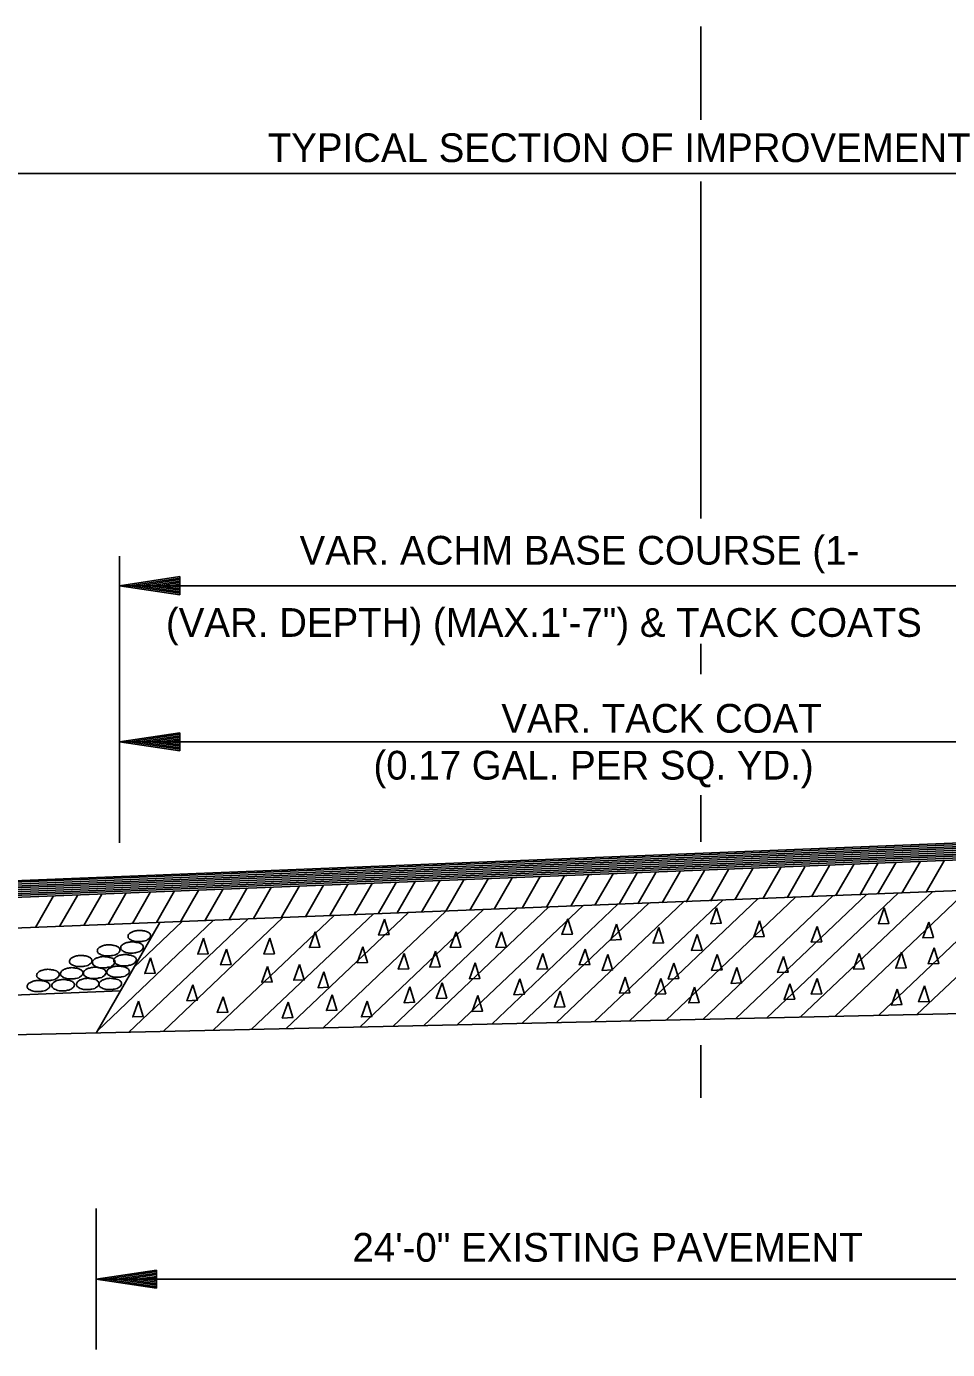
# Model space of a CAD drawing. Extents: x 714919 to 718439, y 1619644 to 1621844.
# Drawn here: x 716443 to 716828, y 1620734 to 1621286 of the extents above; entities that cross this region are included whole.
import ezdxf

# ---------------------------------------------------------------- set-up
doc = ezdxf.new("R2010")
doc.units = 0
doc.layers.add('R_Dimension', color=7, linetype='Continuous')
doc.layers.add('R_Draft', color=7, linetype='Continuous')

msp = doc.modelspace()

# ---------------------------------------------------------------- linework, layer by layer
at = {"layer": 'R_Dimension'}
for p, q in [((716083.88, 1621224.65), (717366.01, 1621224.65)), ((716482.09, 1620945.31), (716482.09, 1621064.99)), ((716507.22, 1621056.42), (716482.09, 1621052.6)), ((716482.09, 1621052.6), (716965.77, 1621052.6)), ((716507.22, 1621048.83), (716482.09, 1621052.6)), ((716507.22, 1621055.74), (716486.27, 1621052.6)), ((716507.22, 1621049.45), (716486.27, 1621052.6)), ((716507.22, 1621055.19), (716490.59, 1621052.6)), ((716507.22, 1621050.06), (716490.59, 1621052.6)), ((716507.22, 1621054.48), (716494.79, 1621052.6)), ((716507.22, 1621050.73), (716494.79, 1621052.6)), ((716507.22, 1621053.88), (716499.05, 1621052.6)), ((716507.22, 1621051.34), (716499.05, 1621052.6)), ((716507.22, 1621053.2), (716503.27, 1621052.6)), ((716507.22, 1621052.04), (716503.27, 1621052.6)), ((716507.22, 1621048.83), (716507.22, 1621056.42)), ((716507.22, 1620991.18), (716482.09, 1620987.43)), ((716482.09, 1620987.43), (716965.77, 1620987.43)), ((716507.22, 1620983.64), (716482.09, 1620987.43)), ((716507.22, 1620990.6), (716486.27, 1620987.43)), ((716507.22, 1620984.32), (716486.27, 1620987.43)), ((716507.22, 1620989.93), (716490.59, 1620987.43)), ((716507.22, 1620984.92), (716490.59, 1620987.43)), ((716507.22, 1620989.35), (716494.79, 1620987.43)), ((716507.22, 1620985.56), (716494.79, 1620987.43)), ((716507.22, 1620988.62), (716499.05, 1620987.43)), ((716507.22, 1620986.2), (716499.05, 1620987.43)), ((716507.22, 1620988.06), (716503.27, 1620987.43)), ((716507.22, 1620986.86), (716503.27, 1620987.43)), ((716507.22, 1620983.64), (716507.22, 1620991.18)), ((716472.35, 1620733.75), (716472.35, 1620792.61)), ((716497.51, 1620766.86), (716472.35, 1620763.08)), ((716497.51, 1620766.26), (716476.54, 1620763.08)), ((716497.51, 1620765.57), (716480.91, 1620763.08)), ((716497.51, 1620765.02), (716485.05, 1620763.08)), ((716497.51, 1620759.32), (716497.51, 1620766.86)), ((716472.35, 1620763.08), (716975.67, 1620763.08)), ((716497.51, 1620759.32), (716472.35, 1620763.08)), ((716497.51, 1620759.97), (716476.54, 1620763.08)), ((716497.51, 1620760.58), (716480.91, 1620763.08)), ((716497.51, 1620761.21), (716485.05, 1620763.08)), ((716497.51, 1620764.29), (716489.36, 1620763.08)), ((716497.51, 1620761.85), (716489.36, 1620763.08)), ((716497.51, 1620763.74), (716493.55, 1620763.08)), ((716497.51, 1620762.51), (716493.55, 1620763.08))]:
    msp.add_line(p, q, dxfattribs=at)
at = {"layer": 'R_Draft'}
for p, q in [((716724.7, 1621247.08), (716724.7, 1621286.06)), ((716724.7, 1621095.46), (716724.7, 1621221.36)), ((716724.7, 1621080.6), (716724.7, 1621095.46)), ((716724.7, 1621015.65), (716724.7, 1621028.27)), ((716077.33, 1620912.05), (717371.84, 1620963.68)), ((716079.01, 1620912.92), (717370.38, 1620964.41)), ((716080.68, 1620913.71), (717368.96, 1620965.14)), ((716082.38, 1620914.6), (717367.45, 1620965.87)), ((716083.88, 1620915.32), (717366.08, 1620966.55)), ((716724.7, 1620945.67), (716724.7, 1620965.11)), ((716273.48, 1620916.69), (717175.48, 1620952.65)), ((716273.96, 1620917.52), (717174.96, 1620953.41)), ((716274.45, 1620918.29), (717173.88, 1620954.11)), ((716274.98, 1620919.1), (717173.88, 1620954.98)), ((716272.93, 1620915.95), (717176, 1620951.88)), ((716264.68, 1620902.75), (717184.57, 1620939.35)), ((716788.45, 1620936.18), (716780.88, 1620923.13)), ((716798.54, 1620936.59), (716790.99, 1620923.47)), ((716805.99, 1620936.98), (716798.4, 1620923.79)), ((716816.15, 1620937.4), (716808.53, 1620924.2)), ((716826.18, 1620937.72), (716818.67, 1620924.68)), ((716645.95, 1620930.68), (716638.41, 1620917.55)), ((716657.63, 1620931.15), (716650.06, 1620917.97)), ((716667.67, 1620931.36), (716660.23, 1620918.44)), ((716677.95, 1620931.95), (716670.34, 1620918.87)), ((716688.02, 1620932.38), (716680.47, 1620919.2)), ((716698.14, 1620932.77), (716690.56, 1620919.62)), ((716705.93, 1620932.93), (716698.39, 1620919.8)), ((716716.08, 1620933.29), (716708.5, 1620920.22)), ((716726.15, 1620933.71), (716718.6, 1620920.56)), ((716736.25, 1620934.18), (716728.73, 1620920.98)), ((716746.37, 1620934.55), (716738.85, 1620921.43)), ((716758.09, 1620934.97), (716750.48, 1620921.83)), ((716768.13, 1620935.2), (716760.71, 1620922.26)), ((716778.31, 1620935.83), (716770.8, 1620922.66)), ((716505.06, 1620925.22), (716497.48, 1620912.08)), ((716515.21, 1620925.62), (716507.67, 1620912.5)), ((716525.27, 1620926.11), (716517.75, 1620912.94)), ((716535.4, 1620926.46), (716527.87, 1620913.31)), ((716545.46, 1620926.85), (716537.94, 1620913.7)), ((716557.19, 1620927.35), (716549.65, 1620914.18)), ((716567.26, 1620927.56), (716559.81, 1620914.6)), ((716577.42, 1620928.11), (716569.9, 1620914.98)), ((716587.57, 1620928.53), (716580.03, 1620915.4)), ((716597.63, 1620928.97), (716590.09, 1620915.85)), ((716605.51, 1620929.07), (716597.95, 1620915.98)), ((716615.71, 1620929.47), (716608.11, 1620916.3)), ((716625.74, 1620929.86), (716618.19, 1620916.74)), ((716635.87, 1620930.3), (716628.32, 1620917.16)), ((716780.54, 1620872.8), (716835.95, 1620925.47)), ((716798.88, 1620873.26), (716854.69, 1620926.28)), ((716814.85, 1620873.6), (716871.1, 1620926.87)), ((716454.51, 1620923.16), (716446.94, 1620909.98)), ((716464.53, 1620923.34), (716457.08, 1620910.4)), ((716474.72, 1620923.89), (716467.18, 1620910.79)), ((716484.88, 1620924.34), (716477.3, 1620911.22)), ((716494.97, 1620924.75), (716487.42, 1620911.64)), ((716637.39, 1620869.6), (716690.01, 1620919.68)), ((716650.01, 1620869.87), (716703.15, 1620920.23)), ((716664.24, 1620870.18), (716717.58, 1620920.72)), ((716680.18, 1620870.54), (716733.98, 1620921.45)), ((716694.69, 1620870.85), (716748.61, 1620922.03)), ((716710.25, 1620871.23), (716764.14, 1620922.61)), ((716725.54, 1620871.56), (716779.84, 1620923.29)), ((716739.32, 1620871.9), (716793.92, 1620923.79)), ((716752.04, 1620872.14), (716807.09, 1620924.34)), ((716766.16, 1620872.46), (716821.42, 1620924.91)), ((716500.28, 1620866.48), (716550.28, 1620914.1)), ((716521.08, 1620867), (716571.65, 1620914.93)), ((716537.05, 1620867.3), (716588.07, 1620915.62)), ((716551.48, 1620867.63), (716602.68, 1620916.16)), ((716567.05, 1620867.98), (716618.27, 1620916.8)), ((716582.33, 1620868.37), (716633.9, 1620917.5)), ((716596.11, 1620868.65), (716648.02, 1620917.97)), ((716608.89, 1620868.92), (716661.19, 1620918.55)), ((716622.99, 1620869.24), (716675.5, 1620919.08)), ((716472.35, 1620865.88), (716498.95, 1620912.07)), ((716472.89, 1620866.82), (716521.35, 1620913)), ((716485.81, 1620866.12), (716535.75, 1620913.49)), ((716488.15, 1620893.32), (716508.22, 1620912.42)), ((715980.19, 1620863.5), (716482.51, 1620883.51)), ((716371.46, 1620863.61), (717076.27, 1620879.47)), ((716724.7, 1620838.78), (716724.7, 1620860.75))]:
    msp.add_line(p, q, dxfattribs=at)
for points in [[(716731.19, 1620918.12), (716728.78, 1620911.49), (716733.17, 1620911.67), (716731.19, 1620918.12)], [(716801.2, 1620918.1), (716798.79, 1620911.47), (716803.18, 1620911.65), (716801.2, 1620918.1)], [(716592.6, 1620913.41), (716590.19, 1620906.78), (716594.58, 1620906.96), (716592.6, 1620913.41)], [(716669.13, 1620913.58), (716666.71, 1620906.95), (716671.1, 1620907.13), (716669.13, 1620913.58)], [(716689.48, 1620911.32), (716687.06, 1620904.69), (716691.46, 1620904.87), (716689.48, 1620911.32)], [(716707.12, 1620909.96), (716704.7, 1620903.33), (716709.1, 1620903.51), (716707.12, 1620909.96)], [(716749.19, 1620912.68), (716746.77, 1620906.05), (716751.16, 1620906.23), (716749.19, 1620912.68)], [(716773.16, 1620910.41), (716770.74, 1620903.78), (716775.14, 1620903.96), (716773.16, 1620910.41)], [(716819.75, 1620912.22), (716817.33, 1620905.59), (716821.72, 1620905.77), (716819.75, 1620912.22)], [(716517.15, 1620905.44), (716514.73, 1620898.81), (716519.12, 1620898.99), (716517.15, 1620905.44)], [(716544.74, 1620905.44), (716542.32, 1620898.81), (716546.72, 1620898.99), (716544.74, 1620905.44)], [(716563.74, 1620908.15), (716561.32, 1620901.52), (716565.71, 1620901.7), (716563.74, 1620908.15)], [(716622.54, 1620908.15), (716620.12, 1620901.52), (716624.51, 1620901.7), (716622.54, 1620908.15)], [(716641.53, 1620908.15), (716639.12, 1620901.52), (716643.51, 1620901.7), (716641.53, 1620908.15)], [(716723.17, 1620906.97), (716720.76, 1620900.34), (716725.15, 1620900.52), (716723.17, 1620906.97)], [(716526.65, 1620900.92), (716524.23, 1620894.29), (716528.62, 1620894.47), (716526.65, 1620900.92)], [(716583.64, 1620901.82), (716581.22, 1620895.19), (716585.61, 1620895.37), (716583.64, 1620901.82)], [(716600.83, 1620899.11), (716598.41, 1620892.48), (716602.8, 1620892.66), (716600.83, 1620899.11)], [(716613.94, 1620900.01), (716611.53, 1620893.38), (716615.92, 1620893.56), (716613.94, 1620900.01)], [(716658.72, 1620899.11), (716656.31, 1620892.48), (716660.7, 1620892.66), (716658.72, 1620899.11)], [(716676.36, 1620900.92), (716673.95, 1620894.29), (716678.34, 1620894.47), (716676.36, 1620900.92)], [(716685.86, 1620898.65), (716683.44, 1620892.02), (716687.84, 1620892.2), (716685.86, 1620898.65)], [(716731.54, 1620898.65), (716729.13, 1620892.02), (716733.52, 1620892.2), (716731.54, 1620898.65)], [(716759.14, 1620897.75), (716756.72, 1620891.12), (716761.11, 1620891.3), (716759.14, 1620897.75)], [(716790.8, 1620899.11), (716788.38, 1620892.48), (716792.78, 1620892.66), (716790.8, 1620899.11)], [(716808.44, 1620899.56), (716806.02, 1620892.93), (716810.42, 1620893.11), (716808.44, 1620899.56)], [(716822.01, 1620901.37), (716819.59, 1620894.74), (716823.99, 1620894.92), (716822.01, 1620901.37)], [(716494.98, 1620897.3), (716492.57, 1620890.67), (716496.96, 1620890.85), (716494.98, 1620897.3)], [(716543.83, 1620893.68), (716541.42, 1620887.05), (716545.81, 1620887.23), (716543.83, 1620893.68)], [(716557.2, 1620894.5), (716554.78, 1620887.87), (716559.17, 1620888.05), (716557.2, 1620894.5)], [(716630.51, 1620895.15), (716628.09, 1620888.52), (716632.49, 1620888.7), (716630.51, 1620895.15)], [(716713.45, 1620895.04), (716711.04, 1620888.41), (716715.43, 1620888.58), (716713.45, 1620895.04)], [(716739.69, 1620893.23), (716737.27, 1620886.6), (716741.66, 1620886.78), (716739.69, 1620893.23)], [(716567.35, 1620891.42), (716564.94, 1620884.79), (716569.33, 1620884.97), (716567.35, 1620891.42)], [(716616.66, 1620886.89), (716614.24, 1620880.26), (716618.63, 1620880.44), (716616.66, 1620886.89)], [(716649.07, 1620888.49), (716646.65, 1620881.86), (716651.05, 1620882.03), (716649.07, 1620888.49)], [(716693.1, 1620889.16), (716690.68, 1620882.53), (716695.08, 1620882.7), (716693.1, 1620889.16)], [(716708.02, 1620888.7), (716705.61, 1620882.07), (716710, 1620882.25), (716708.02, 1620888.7)], [(716761.85, 1620886.44), (716759.43, 1620879.81), (716763.83, 1620879.99), (716761.85, 1620886.44)], [(716773.16, 1620888.7), (716770.74, 1620882.07), (716775.14, 1620882.25), (716773.16, 1620888.7)], [(716512.62, 1620885.99), (716510.21, 1620879.36), (716514.6, 1620879.54), (716512.62, 1620885.99)], [(716525.29, 1620881.01), (716522.87, 1620874.38), (716527.27, 1620874.56), (716525.29, 1620881.01)], [(716570.8, 1620881.87), (716568.38, 1620875.23), (716572.77, 1620875.41), (716570.8, 1620881.87)], [(716603.23, 1620885.16), (716600.81, 1620878.53), (716605.21, 1620878.71), (716603.23, 1620885.16)], [(716631.58, 1620881.47), (716629.17, 1620874.84), (716633.56, 1620875.02), (716631.58, 1620881.47)], [(716665.96, 1620883.28), (716663.54, 1620876.64), (716667.94, 1620876.82), (716665.96, 1620883.28)], [(716722.05, 1620885.08), (716719.63, 1620878.45), (716724.02, 1620878.63), (716722.05, 1620885.08)], [(716806.63, 1620884.18), (716804.21, 1620877.55), (716808.61, 1620877.73), (716806.63, 1620884.18)], [(716817.94, 1620885.54), (716815.52, 1620878.91), (716819.91, 1620879.09), (716817.94, 1620885.54)], [(716490.01, 1620879.2), (716487.59, 1620872.57), (716491.98, 1620872.75), (716490.01, 1620879.2)], [(716552.43, 1620878.75), (716550.01, 1620872.12), (716554.4, 1620872.3), (716552.43, 1620878.75)], [(716585.45, 1620879.2), (716583.03, 1620872.57), (716587.42, 1620872.75), (716585.45, 1620879.2)]]:
    msp.add_lwpolyline(points, dxfattribs=at)
for points in [[(716490.32, 1620904.05), (716488.64, 1620904.08), (716486.81, 1620904.73), (716485.74, 1620905.63), (716485.63, 1620906.15), (716486.06, 1620907.27), (716486.69, 1620907.74), (716487.76, 1620908.27), (716489.4, 1620908.64), (716490.17, 1620908.72), (716491.45, 1620908.61), (716492.83, 1620908.4), (716493.89, 1620908.03), (716494.9, 1620907.17), (716495.07, 1620906.6), (716494.78, 1620905.67), (716494.02, 1620904.99), (716493.26, 1620904.52), (716492.11, 1620904.24), (716491.39, 1620904.08), (716490.32, 1620904.05)], [(716487.24, 1620899.26), (716485.56, 1620899.29), (716483.73, 1620899.94), (716482.66, 1620900.84), (716482.55, 1620901.36), (716482.98, 1620902.48), (716483.62, 1620902.95), (716484.68, 1620903.48), (716486.32, 1620903.85), (716487.09, 1620903.93), (716488.37, 1620903.82), (716489.75, 1620903.61), (716490.81, 1620903.24), (716491.82, 1620902.38), (716491.99, 1620901.82), (716491.7, 1620900.88), (716490.94, 1620900.2), (716490.18, 1620899.73), (716489.03, 1620899.45), (716488.31, 1620899.29), (716487.24, 1620899.26)], [(716465.86, 1620893.61), (716464.17, 1620893.65), (716462.35, 1620894.29), (716461.28, 1620895.2), (716461.17, 1620895.72), (716461.6, 1620896.83), (716462.23, 1620897.3), (716463.3, 1620897.84), (716464.93, 1620898.21), (716465.71, 1620898.29), (716466.99, 1620898.18), (716468.36, 1620897.97), (716469.43, 1620897.59), (716470.43, 1620896.74), (716470.61, 1620896.17), (716470.32, 1620895.23), (716469.56, 1620894.55), (716468.8, 1620894.08), (716467.65, 1620893.81), (716466.92, 1620893.65), (716465.86, 1620893.61)], [(716475.44, 1620893.1), (716473.75, 1620893.13), (716471.93, 1620893.78), (716470.86, 1620894.69), (716470.74, 1620895.2), (716471.18, 1620896.32), (716471.81, 1620896.79), (716472.88, 1620897.32), (716474.51, 1620897.7), (716475.29, 1620897.78), (716476.57, 1620897.66), (716477.94, 1620897.45), (716479.01, 1620897.08), (716480.01, 1620896.22), (716480.19, 1620895.66), (716479.9, 1620894.72), (716479.14, 1620894.04), (716478.38, 1620893.57), (716477.23, 1620893.3), (716476.5, 1620893.13), (716475.44, 1620893.1)], [(716477.49, 1620898.06), (716475.81, 1620898.09), (716473.98, 1620898.74), (716472.91, 1620899.65), (716472.8, 1620900.16), (716473.23, 1620901.28), (716473.87, 1620901.75), (716474.93, 1620902.28), (716476.57, 1620902.66), (716477.34, 1620902.74), (716478.62, 1620902.62), (716480, 1620902.41), (716481.06, 1620902.04), (716482.07, 1620901.18), (716482.24, 1620900.62), (716481.95, 1620899.68), (716481.19, 1620899), (716480.43, 1620898.53), (716479.28, 1620898.26), (716478.56, 1620898.09), (716477.49, 1620898.06)], [(716484.33, 1620893.96), (716482.65, 1620893.99), (716480.82, 1620894.64), (716479.75, 1620895.54), (716479.64, 1620896.06), (716480.08, 1620897.18), (716480.71, 1620897.64), (716481.77, 1620898.18), (716483.41, 1620898.55), (716484.19, 1620898.63), (716485.46, 1620898.52), (716486.84, 1620898.31), (716487.91, 1620897.94), (716488.91, 1620897.08), (716489.09, 1620896.51), (716488.8, 1620895.57), (716488.04, 1620894.89), (716487.28, 1620894.43), (716486.13, 1620894.15), (716485.4, 1620893.99), (716484.33, 1620893.96)], [(716452.17, 1620887.8), (716450.49, 1620887.83), (716448.66, 1620888.48), (716447.59, 1620889.38), (716447.48, 1620889.9), (716447.92, 1620891.02), (716448.55, 1620891.49), (716449.62, 1620892.02), (716451.25, 1620892.39), (716452.03, 1620892.47), (716453.3, 1620892.36), (716454.68, 1620892.15), (716455.75, 1620891.78), (716456.75, 1620890.92), (716456.93, 1620890.35), (716456.64, 1620889.42), (716455.88, 1620888.74), (716455.12, 1620888.27), (716453.97, 1620887.99), (716453.24, 1620887.83), (716452.17, 1620887.8)], [(716462.09, 1620888.48), (716460.41, 1620888.52), (716458.58, 1620889.16), (716457.52, 1620890.07), (716457.4, 1620890.59), (716457.84, 1620891.7), (716458.47, 1620892.17), (716459.54, 1620892.71), (716461.17, 1620893.08), (716461.95, 1620893.16), (716463.23, 1620893.04), (716464.6, 1620892.83), (716465.67, 1620892.46), (716466.67, 1620891.61), (716466.85, 1620891.04), (716466.56, 1620890.1), (716465.8, 1620889.42), (716465.04, 1620888.95), (716463.89, 1620888.68), (716463.16, 1620888.52), (716462.09, 1620888.48)], [(716471.67, 1620888.65), (716469.99, 1620888.69), (716468.16, 1620889.33), (716467.09, 1620890.24), (716466.98, 1620890.76), (716467.42, 1620891.87), (716468.05, 1620892.34), (716469.12, 1620892.88), (716470.75, 1620893.25), (716471.53, 1620893.33), (716472.81, 1620893.22), (716474.18, 1620893.01), (716475.25, 1620892.63), (716476.25, 1620891.78), (716476.43, 1620891.21), (716476.14, 1620890.27), (716475.38, 1620889.59), (716474.62, 1620889.12), (716473.47, 1620888.85), (716472.74, 1620888.69), (716471.67, 1620888.65)], [(716481.42, 1620889.17), (716479.74, 1620889.2), (716477.91, 1620889.85), (716476.84, 1620890.75), (716476.73, 1620891.27), (716477.17, 1620892.39), (716477.8, 1620892.86), (716478.87, 1620893.39), (716480.5, 1620893.76), (716481.28, 1620893.84), (716482.56, 1620893.73), (716483.93, 1620893.52), (716485, 1620893.15), (716486, 1620892.29), (716486.18, 1620891.72), (716485.89, 1620890.78), (716485.13, 1620890.11), (716484.37, 1620889.64), (716483.22, 1620889.36), (716482.49, 1620889.2), (716481.42, 1620889.17)], [(716448.24, 1620883.18), (716446.56, 1620883.21), (716444.73, 1620883.86), (716443.66, 1620884.77), (716443.55, 1620885.28), (716443.98, 1620886.4), (716444.61, 1620886.87), (716445.68, 1620887.4), (716447.32, 1620887.77), (716448.09, 1620887.86), (716449.37, 1620887.74), (716450.75, 1620887.53), (716451.81, 1620887.16), (716452.82, 1620886.3), (716452.99, 1620885.74), (716452.7, 1620884.8), (716451.94, 1620884.12), (716451.18, 1620883.65), (716450.03, 1620883.37), (716449.31, 1620883.21), (716448.24, 1620883.18)], [(716458.5, 1620883.52), (716456.82, 1620883.55), (716454.99, 1620884.2), (716453.92, 1620885.11), (716453.81, 1620885.63), (716454.25, 1620886.74), (716454.88, 1620887.21), (716455.95, 1620887.74), (716457.58, 1620888.12), (716458.36, 1620888.2), (716459.63, 1620888.08), (716461.01, 1620887.87), (716462.08, 1620887.5), (716463.08, 1620886.64), (716463.26, 1620886.08), (716462.97, 1620885.14), (716462.21, 1620884.46), (716461.45, 1620883.99), (716460.3, 1620883.72), (716459.57, 1620883.55), (716458.5, 1620883.52)], [(716468.76, 1620884.04), (716467.08, 1620884.07), (716465.25, 1620884.71), (716464.19, 1620885.62), (716464.07, 1620886.14), (716464.51, 1620887.25), (716465.14, 1620887.72), (716466.21, 1620888.26), (716467.84, 1620888.63), (716468.62, 1620888.71), (716469.9, 1620888.6), (716471.27, 1620888.39), (716472.34, 1620888.02), (716473.34, 1620887.16), (716473.52, 1620886.59), (716473.23, 1620885.65), (716472.47, 1620884.97), (716471.71, 1620884.5), (716470.56, 1620884.23), (716469.83, 1620884.07), (716468.76, 1620884.04)], [(716478.17, 1620884.04), (716476.49, 1620884.07), (716474.66, 1620884.71), (716473.59, 1620885.62), (716473.48, 1620886.14), (716473.92, 1620887.25), (716474.55, 1620887.72), (716475.62, 1620888.26), (716477.25, 1620888.63), (716478.03, 1620888.71), (716479.31, 1620888.6), (716480.68, 1620888.39), (716481.75, 1620888.02), (716482.75, 1620887.16), (716482.93, 1620886.59), (716482.64, 1620885.65), (716481.88, 1620884.97), (716481.12, 1620884.5), (716479.97, 1620884.23), (716479.24, 1620884.07), (716478.17, 1620884.04)]]:
    msp.add_spline(points, degree=3, dxfattribs=at)

# ---------------------------------------------------------------- texts
at = {"layer": 'R_Dimension'}
for s, p in [('TYPICAL SECTION OF IMPROVEMENT', (716543.92, 1621229.44)), ('VAR. ACHM BASE COURSE (1-', (716557.2, 1621061.4)), ('(VAR. DEPTH) (MAX.1\'-7") & TACK COATS', (716501.43, 1621031.26)), ('VAR. TACK COAT', (716641.39, 1620991.24)), ('(0.17 GAL. PER SQ. YD.)', (716588.04, 1620971.67)), ('24\'-0" EXISTING PAVEMENT', (716579.28, 1620770.41))]:
    msp.add_text(s, height=12, dxfattribs=at).set_placement(p)

doc.saveas('drawing.dxf')
